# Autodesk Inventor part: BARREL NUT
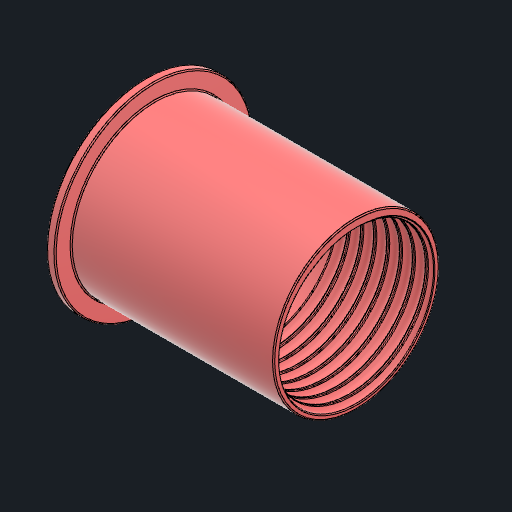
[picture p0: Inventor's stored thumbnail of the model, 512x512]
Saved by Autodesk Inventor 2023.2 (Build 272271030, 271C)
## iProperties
Created: 2022-12
Part Number: BARREL NUT
Material: Generic
Document SubType Name: Modeling
Designer: AR
Mass: 12.1734 g
Surface Area: 145.28 cm^2
Volume: 12.1734 cm^3
Density: 1 g/cm^3
Appearance: Smooth - Purple
Author: AR
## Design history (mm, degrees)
derived "_2 SPOOL CORD WRAP MP.ipt"
feature "PRUSA BARREL NUT::_2 SPOOL CORD WRAP MP.ipt" dims "d0" = 10
tag "TaggingFeature1"
node "PRUSA BARREL NUT"
